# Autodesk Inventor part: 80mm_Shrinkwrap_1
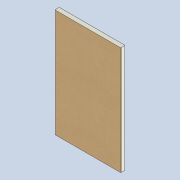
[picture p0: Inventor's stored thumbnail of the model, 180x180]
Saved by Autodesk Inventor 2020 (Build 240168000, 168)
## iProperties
Created: 2020-11
Part Number: 80mm_Shrinkwrap_1
Material: Generic
Document SubType Name: Modeling
Designer: Yolande
Density: 1 g/cm^3
Appearance: Default
Author: Yolande
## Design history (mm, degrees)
derived "80mm.iam"
body "Solid1"
node "Lambdaboard 80mm Kraft.ipt:1" dims "d0" = 10
